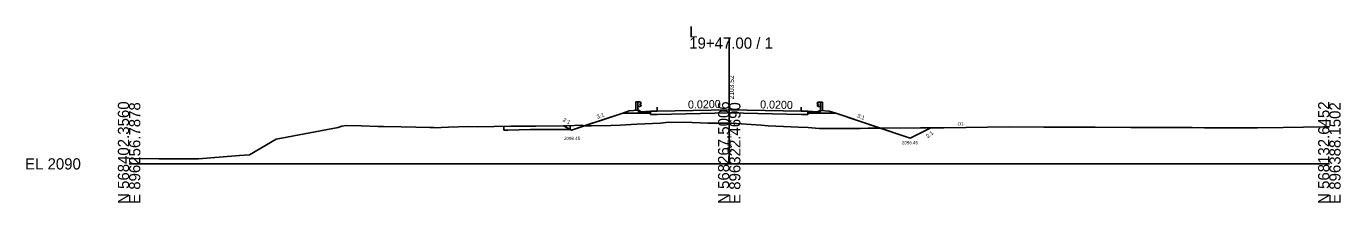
# Model space of a CAD drawing. Extents: x -26 to 1603, y -10 to 13527.
# Drawn here: x 1274.3 to 1602.8, y 490.3 to 534.4 of the extents above; entities that cross this region are included whole.
import ezdxf

# ---------------------------------------------------------------- set-up
doc = ezdxf.new("R2010")
doc.units = 0
for name, color, linetype in [('Default', 7, 'Continuous'), ('Exist XS Center Line Elevation Label', 7, 'Continuous'), ('Exist XS Ground Line', 7, 'Continuous'), ('Old_Level_3', 7, 'Continuous'), ('Old_Level_61', 7, 'Continuous'), ('Old_Level_63', 7, 'Continuous'), ('Prop XS Ditch Slope Text', 7, 'Continuous'), ('Prop XS Ditch Standard Text', 7, 'Continuous'), ('Prop XS Dump Level', 7, 'Continuous'), ('Prop XS Earthwork Shape', 7, 'Continuous'), ('Prop XS EOT Tick Mark', 7, 'Continuous'), ('Prop XS Finish Grade', 7, 'Continuous'), ('Prop XS Finish Grade Earthwork', 7, 'Continuous'), ('Prop XS Finish Grade Paved Shoulder', 7, 'Continuous'), ('Prop XS Finish Grade Pavement', 7, 'Continuous'), ('Prop XS Side Slope Text', 7, 'Continuous'), ('Prop XS Subgrade Earthwork', 7, 'Continuous'), ('Prop XSC Text', 7, 'Continuous'), ('Typical Curb CELL', 7, 'Continuous')]:
    doc.layers.add(name, color=color, linetype=linetype)

msp = doc.modelspace()

# ---------------------------------------------------------------- linework, layer by layer
at = {"layer": 'Exist XS Ground Line'}
for p, q in [((1352.23, 509.13), (1353.15, 509.4)), ((1352.23, 509.13), (1353.15, 509.4)), ((1353.15, 509.4), (1354.28, 509.57)), ((1353.15, 509.4), (1354.28, 509.57)), ((1354.28, 509.57), (1358.01, 509.51)), ((1354.28, 509.57), (1358.01, 509.51)), ((1358.01, 509.51), (1362.25, 509.37)), ((1358.01, 509.51), (1362.25, 509.37)), ((1362.25, 509.37), (1363.55, 509.38)), ((1362.25, 509.37), (1363.55, 509.38)), ((1363.55, 509.38), (1367.97, 509.22)), ((1363.55, 509.38), (1367.97, 509.22)), ((1379.83, 509.18), (1384.78, 509.31)), ((1379.83, 509.18), (1384.78, 509.31)), ((1384.78, 509.31), (1387.05, 509.25)), ((1384.78, 509.31), (1387.05, 509.25)), ((1387.05, 509.25), (1395.41, 509.45)), ((1387.05, 509.25), (1395.41, 509.45)), ((1395.41, 509.45), (1401.64, 509.44)), ((1401.64, 509.44), (1409.38, 509.47)), ((1409.38, 509.47), (1413.18, 509.68)), ((1409.38, 509.47), (1413.18, 509.68)), ((1413.18, 509.68), (1413.82, 509.49)), ((1413.18, 509.68), (1413.82, 509.49)), ((1413.82, 509.49), (1415.62, 509.51)), ((1413.82, 509.49), (1415.62, 509.51)), ((1415.62, 509.51), (1420.4, 509.62)), ((1415.62, 509.51), (1420.4, 509.62)), ((1420.4, 509.62), (1422.73, 509.68)), ((1420.4, 509.62), (1422.73, 509.68)), ((1422.73, 509.68), (1426.87, 509.91)), ((1422.73, 509.68), (1426.87, 509.91)), ((1426.87, 509.91), (1432.79, 510.21)), ((1426.87, 509.91), (1432.79, 510.21)), ((1432.79, 510.21), (1434.19, 510.32)), ((1432.79, 510.21), (1434.19, 510.32)), ((1434.19, 510.32), (1434.93, 510.4)), ((1434.19, 510.32), (1434.93, 510.4)), ((1434.93, 510.4), (1435.54, 510.31)), ((1434.93, 510.4), (1435.54, 510.31)), ((1435.54, 510.31), (1438.86, 510.41)), ((1435.54, 510.31), (1438.86, 510.41)), ((1438.86, 510.41), (1444.63, 510.2)), ((1438.86, 510.41), (1444.63, 510.2)), ((1444.63, 510.2), (1449.41, 510.2)), ((1444.63, 510.2), (1449.41, 510.2)), ((1449.41, 510.2), (1450, 510.17)), ((1449.41, 510.2), (1450, 510.17)), ((1450, 510.17), (1450.6, 510.14)), ((1450, 510.17), (1450.6, 510.14)), ((1450.6, 510.14), (1457.97, 509.65)), ((1450.6, 510.14), (1457.97, 509.65)), ((1457.97, 509.65), (1459.71, 509.53)), ((1457.97, 509.65), (1459.71, 509.53)), ((1459.71, 509.53), (1463.59, 509.3)), ((1459.71, 509.53), (1463.59, 509.3)), ((1463.59, 509.3), (1467.2, 509.17)), ((1463.59, 509.3), (1467.2, 509.17)), ((1503.63, 509.04), (1520.07, 509.27)), ((1503.63, 509.04), (1520.07, 509.27)), ((1520.07, 509.27), (1528.65, 509.21)), ((1520.07, 509.27), (1528.65, 509.21)), ((1588.45, 509.09), (1598.61, 509.28)), ((1588.45, 509.09), (1598.61, 509.28)), ((1598.61, 509.28), (1600, 509.29)), ((1598.61, 509.28), (1600, 509.29)), ((1330.13, 502.3), (1336.79, 506.21)), ((1330.13, 502.3), (1336.79, 506.21)), ((1336.79, 506.21), (1352.23, 509.13)), ((1336.79, 506.21), (1352.23, 509.13)), ((1367.97, 509.22), (1371.71, 509.15)), ((1367.97, 509.22), (1371.71, 509.15)), ((1371.71, 509.15), (1375.13, 509.07)), ((1371.71, 509.15), (1375.13, 509.07)), ((1375.13, 509.07), (1376.18, 509.07)), ((1375.13, 509.07), (1376.18, 509.07)), ((1376.18, 509.07), (1376.92, 509.02)), ((1376.18, 509.07), (1376.92, 509.02)), ((1376.92, 509.02), (1377.97, 509.07)), ((1376.92, 509.02), (1377.97, 509.07)), ((1377.97, 509.07), (1379.83, 509.18)), ((1377.97, 509.07), (1379.83, 509.18)), ((1467.2, 509.17), (1469.74, 509.09)), ((1467.2, 509.17), (1469.74, 509.09)), ((1469.74, 509.09), (1472.45, 508.85)), ((1469.74, 509.09), (1472.45, 508.85)), ((1472.45, 508.85), (1473.17, 508.81)), ((1472.45, 508.85), (1473.17, 508.81)), ((1473.17, 508.81), (1482.71, 508.88)), ((1473.17, 508.81), (1482.71, 508.88)), ((1482.71, 508.88), (1484.77, 508.89)), ((1482.71, 508.88), (1484.77, 508.89)), ((1484.77, 508.89), (1497.82, 509.03)), ((1484.77, 508.89), (1497.82, 509.03)), ((1497.82, 509.03), (1502.01, 509.04)), ((1497.82, 509.03), (1502.01, 509.04)), ((1502.01, 509.04), (1503.63, 509.04)), ((1502.01, 509.04), (1503.63, 509.04)), ((1528.65, 509.21), (1536.58, 509.19)), ((1528.65, 509.21), (1536.58, 509.19)), ((1536.58, 509.19), (1541.49, 509.19)), ((1536.58, 509.19), (1541.49, 509.19)), ((1541.49, 509.19), (1550.41, 509.13)), ((1541.49, 509.19), (1550.41, 509.13)), ((1550.41, 509.13), (1554.1, 509.09)), ((1550.41, 509.13), (1554.1, 509.09)), ((1554.1, 509.09), (1565.7, 509.07)), ((1554.1, 509.09), (1565.7, 509.07)), ((1565.7, 509.07), (1568.76, 508.98)), ((1565.7, 509.07), (1568.76, 508.98)), ((1568.76, 508.98), (1582.06, 508.97)), ((1568.76, 508.98), (1582.06, 508.97)), ((1582.06, 508.97), (1588.45, 509.09)), ((1582.06, 508.97), (1588.45, 509.09)), ((1300, 501.37), (1307.43, 501.29)), ((1300, 501.37), (1307.43, 501.29)), ((1307.43, 501.29), (1317.39, 501.27)), ((1307.43, 501.29), (1317.39, 501.27)), ((1317.39, 501.27), (1326.58, 502)), ((1317.39, 501.27), (1326.58, 502)), ((1326.58, 502), (1327.56, 502.06)), ((1326.58, 502), (1327.56, 502.06)), ((1327.56, 502.06), (1330.13, 502.3)), ((1327.56, 502.06), (1330.13, 502.3))]:
    msp.add_line(p, q, dxfattribs=at)
at = {"layer": 'Old_Level_3'}
for p, q in [((1426.69, 513.35), (1426.69, 515.46)), ((1426.69, 515.46), (1427.19, 515.46)), ((1427.19, 515.46), (1427.19, 513.38)), ((1427.19, 515.46), (1427.69, 515.46)), ((1427.69, 514.32), (1427.19, 514.32)), ((1427.69, 515.46), (1427.98, 515.26)), ((1427.98, 515.14), (1427.69, 514.94)), ((1427.69, 514.94), (1427.69, 514.84)), ((1427.69, 514.84), (1427.98, 514.64)), ((1427.98, 514.52), (1427.69, 514.32)), ((1427.98, 515.26), (1428.01, 515.2)), ((1428.01, 515.2), (1427.98, 515.14)), ((1427.98, 514.64), (1428.01, 514.58)), ((1428.01, 514.58), (1427.98, 514.52)), ((1472.02, 515.24), (1471.99, 515.18)), ((1471.99, 515.18), (1472.02, 515.12)), ((1472.02, 514.62), (1471.99, 514.56)), ((1471.99, 514.56), (1472.02, 514.5)), ((1472.31, 515.44), (1472.02, 515.24)), ((1472.02, 515.12), (1472.31, 514.92)), ((1472.31, 514.82), (1472.02, 514.62)), ((1472.02, 514.5), (1472.31, 514.3)), ((1472.81, 515.44), (1472.31, 515.44)), ((1472.31, 514.92), (1472.31, 514.82)), ((1472.31, 514.3), (1472.81, 514.3)), ((1473.31, 515.44), (1472.81, 515.44)), ((1472.81, 515.44), (1472.81, 513.31)), ((1473.31, 513.28), (1473.31, 515.44))]:
    msp.add_line(p, q, dxfattribs=at)
at = {"layer": 'Old_Level_61'}
for p, q in [((1393.65, 509.41), (1393.65, 508.41)), ((1410.22, 508.55), (1410.22, 509.52)), ((1393.65, 508.41), (1394.65, 508.44)), ((1394.65, 508.44), (1400.32, 508.57)), ((1400.32, 508.57), (1401.83, 508.61)), ((1401.83, 508.61), (1403.36, 508.58)), ((1403.36, 508.58), (1410.22, 508.55))]:
    msp.add_line(p, q, dxfattribs=at)
at = {"layer": 'Old_Level_63'}
for p, q in [((1450, 500), (1450, 531.57)), ((1300, 500), (1450, 500)), ((1450, 500), (1600, 500))]:
    msp.add_line(p, q, dxfattribs=at)
at = {"layer": 'Prop XS Earthwork Shape'}
for points in [[(1459.71, 509.53), (1463.59, 509.3), (1467.2, 509.17), (1469.74, 509.09), (1472.45, 508.85), (1473.17, 508.81), (1482.71, 508.88), (1484.77, 508.89), (1487.77, 508.93), (1476.62, 512.64), (1472.68, 512.64), (1469.66, 512.71), (1469.65, 512.34), (1468, 512.37), (1450, 512.73), (1432, 512.37), (1430.35, 512.34), (1430.34, 512.71), (1427.32, 512.71), (1423.38, 512.71), (1413.77, 509.51), (1413.82, 509.49), (1415.62, 509.51), (1420.4, 509.62), (1422.73, 509.68), (1426.87, 509.91), (1432.79, 510.21), (1434.19, 510.32), (1434.93, 510.4), (1435.54, 510.31), (1438.86, 510.41), (1444.63, 510.2), (1449.41, 510.2), (1450, 510.17), (1450.6, 510.14), (1457.97, 509.65)], [(1408.57, 509.47), (1409.38, 509.47), (1413.18, 509.68), (1413.77, 509.51), (1410.6, 508.45)], [(1487.77, 508.93), (1497.82, 509.03), (1500.36, 509.03), (1495.2, 506.45)]]:
    msp.add_lwpolyline(points, close=True, dxfattribs=at)
at = {"layer": 'Prop XS EOT Tick Mark'}
for p, q in [((1432, 513.16), (1432, 514.16)), ((1432, 513.16), (1432, 514.16)), ((1432, 513.16), (1432, 514.16)), ((1468, 513.16), (1468, 514.16)), ((1468, 513.16), (1468, 514.16))]:
    msp.add_line(p, q, dxfattribs=at)
at = {"layer": 'Prop XS Finish Grade'}
for p, q in [((1425, 513.25), (1423.38, 512.71)), ((1427.32, 513.39), (1425, 513.25)), ((1428.01, 513.04), (1427.32, 513.39)), ((1472.7, 513.32), (1475, 513.18)), ((1475, 513.18), (1476.62, 512.64))]:
    msp.add_line(p, q, dxfattribs=at)
at = {"layer": 'Prop XS Finish Grade Earthwork'}
for p, q in [((1423.38, 512.71), (1410.6, 508.45)), ((1476.62, 512.64), (1495.2, 506.45)), ((1410.6, 508.45), (1408.57, 509.47)), ((1495.2, 506.45), (1500.36, 509.03))]:
    msp.add_line(p, q, dxfattribs=at)
at = {"layer": 'Prop XS Finish Grade Paved Shoulder'}
for p, q in [((1432, 513.16), (1430.33, 513.13)), ((1468, 513.16), (1469.67, 513.13))]:
    msp.add_line(p, q, dxfattribs=at)
at = {"layer": 'Prop XS Finish Grade Pavement'}
for p, q in [((1432, 513.16), (1450, 513.52)), ((1450, 513.52), (1468, 513.16))]:
    msp.add_line(p, q, dxfattribs=at)
at = {"layer": 'Prop XS Subgrade Earthwork'}
for p, q in [((1427.32, 512.71), (1423.38, 512.71)), ((1430.34, 512.71), (1427.32, 512.71)), ((1430.35, 512.34), (1430.34, 512.71)), ((1450, 512.73), (1432, 512.37)), ((1468, 512.37), (1450, 512.73)), ((1469.65, 512.34), (1469.66, 512.71)), ((1472.68, 512.64), (1469.66, 512.71)), ((1472.68, 512.64), (1476.62, 512.64)), ((1432, 512.37), (1430.35, 512.34)), ((1468, 512.37), (1469.65, 512.34))]:
    msp.add_line(p, q, dxfattribs=at)
at = {"layer": 'Typical Curb CELL'}
for p, q in [((1427.32, 512.71), (1427.32, 513.39)), ((1428.01, 513.04), (1427.32, 513.39)), ((1427.32, 512.71), (1430.34, 512.71)), ((1427.36, 513.01), (1427.51, 513.05)), ((1427.49, 512.96), (1427.36, 513.01)), ((1427.51, 513.05), (1427.49, 512.96)), ((1428.03, 512.93), (1427.92, 512.85)), ((1427.92, 512.85), (1428.09, 512.81)), ((1430.33, 513.13), (1428.01, 513.04)), ((1428.09, 512.81), (1428.03, 512.93)), ((1428.77, 512.98), (1428.73, 512.87)), ((1428.73, 512.87), (1428.85, 512.86)), ((1428.85, 512.86), (1428.77, 512.98)), ((1429.28, 512.93), (1429.17, 512.85)), ((1429.17, 512.85), (1429.34, 512.81)), ((1429.34, 512.81), (1429.28, 512.93)), ((1430.02, 512.98), (1429.98, 512.87)), ((1429.98, 512.87), (1430.1, 512.86)), ((1430.1, 512.86), (1430.02, 512.98)), ((1430.34, 513.13), (1430.34, 513.13)), ((1430.34, 512.71), (1430.34, 513.12)), ((1469.66, 512.71), (1469.67, 513.12)), ((1472.68, 512.64), (1469.66, 512.71)), ((1469.67, 513.13), (1469.67, 513.13)), ((1469.68, 513.13), (1472, 512.99)), ((1469.9, 512.86), (1469.99, 512.97)), ((1470.02, 512.86), (1469.9, 512.86)), ((1469.99, 512.97), (1470.02, 512.86)), ((1470.67, 512.79), (1470.73, 512.9)), ((1470.83, 512.82), (1470.67, 512.79)), ((1470.73, 512.9), (1470.83, 512.82)), ((1471.15, 512.83), (1471.24, 512.95)), ((1471.27, 512.83), (1471.15, 512.83)), ((1471.24, 512.95), (1471.27, 512.83)), ((1471.91, 512.76), (1471.98, 512.87)), ((1472.08, 512.8), (1471.91, 512.76)), ((1471.98, 512.87), (1472.08, 512.8)), ((1472, 512.99), (1472.7, 513.32)), ((1472.5, 512.99), (1472.51, 512.9)), ((1472.65, 512.94), (1472.5, 512.99)), ((1472.51, 512.9), (1472.65, 512.94)), ((1472.68, 512.64), (1472.7, 513.32))]:
    msp.add_line(p, q, dxfattribs=at)
for centre in [(1427.39, 513.09), (1427.48, 512.82), (1427.6, 512.87), (1427.86, 512.9), (1427.88, 512.85), (1428.05, 512.76), (1428.08, 512.87), (1428.28, 512.83), (1428.32, 512.94), (1428.45, 512.91), (1428.48, 512.79), (1428.54, 512.82), (1428.73, 512.82), (1428.85, 512.87), (1428.94, 512.86), (1429.04, 512.82), (1429.1, 512.96), (1429.11, 512.9), (1429.13, 512.85), (1429.33, 512.87), (1429.52, 512.83), (1429.57, 512.94), (1429.62, 512.91), (1429.7, 512.91), (1429.73, 512.79), (1429.79, 512.82), (1429.85, 513), (1430.21, 513.07), (1430.25, 512.95), (1469.76, 512.95), (1469.8, 513.07), (1470.16, 512.99), (1470.22, 512.81), (1470.27, 512.77), (1470.31, 512.9), (1470.38, 512.9), (1470.43, 512.92), (1470.48, 512.81), (1470.67, 512.84), (1470.88, 512.82), (1470.9, 512.87), (1470.91, 512.93), (1470.96, 512.79), (1471.06, 512.83), (1471.15, 512.84), (1471.27, 512.79), (1471.47, 512.78), (1471.52, 512.75), (1471.56, 512.87), (1471.68, 512.9), (1471.73, 512.78), (1471.92, 512.82), (1471.95, 512.71), (1472.13, 512.79), (1472.15, 512.84), (1472.4, 512.81), (1472.52, 512.76), (1472.62, 513.03)]:
    msp.add_circle(centre, 0.00802, dxfattribs=at)
for centre, start, end in [((1430.33, 513.12), 0, 92.048), ((1469.68, 513.12), 86.6704, 178.7184)]:
    msp.add_arc(centre, 0.0104, start, end, dxfattribs=at)

# ---------------------------------------------------------------- texts
at = {"layer": 'Default'}
for rotation, p in [(1.1458, (1439.71, 513.81)), (358.8542, (1457.71, 513.87))]:
    msp.add_text('0.0200', height=2, rotation=rotation, dxfattribs=at).set_placement(p)
at = {"layer": 'Exist XS Center Line Elevation Label'}
msp.add_text('2100.17', height=1, rotation=90, dxfattribs=at).set_placement((1450.5, 502.89))
at = {"layer": 'Old_Level_63'}
for s, p in [('L', (1440, 531.57)), ('19+47.00 / 1', (1440, 528.77)), ('EL 2090', (1274, 498.6))]:
    msp.add_text(s, height=2.8, dxfattribs=at).set_placement(p)
for s, p in [('N 568402.3560', (1300, 490)), ('E 896256.7878', (1302.8, 490)), ('N 568267.5006', (1450, 490)), ('E 896322.4690', (1452.8, 490)), ('N 568132.6452', (1600, 490)), ('E 896388.1502', (1602.8, 490))]:
    msp.add_text(s, height=2.8, rotation=90, dxfattribs=at).set_placement(p)
at = {"layer": 'Prop XS Ditch Slope Text'}
msp.add_text('3:1', height=1, rotation=18.8342, dxfattribs=at).set_placement((1417.07, 511.24))
at = {"layer": 'Prop XS Ditch Standard Text'}
for s, p in [('-D1-', (1506.79, 509.62)), ('2098.45', (1408.73, 505.96)), ('2096.45', (1493.18, 504.9))]:
    msp.add_text(s, height=0.8, dxfattribs=at).set_placement(p)
at = {"layer": 'Prop XS Dump Level'}
msp.add_text('Case1', height=0.04, dxfattribs=at).set_placement((1472, 512.81))
at = {"layer": 'Prop XS Side Slope Text'}
for s, rotation, p in [('2:1', 333.4443, (1408.31, 510.71)), ('3:1', 339.4225, (1481.86, 511.64)), ('2:1', 37.5433, (1499.64, 506.37))]:
    msp.add_text(s, height=1, rotation=rotation, dxfattribs=at).set_placement(p)
at = {"layer": 'Prop XSC Text'}
msp.add_text('2103.52', height=1.2, rotation=90, dxfattribs=at).set_placement((1451.2, 516.11))

doc.saveas('drawing.dxf')
